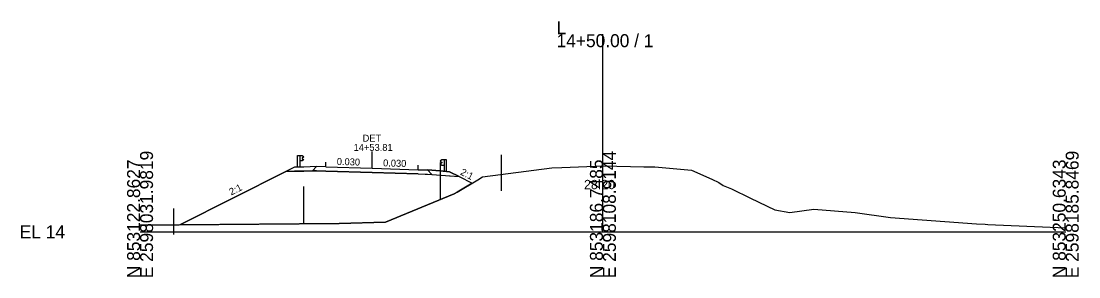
# Model space of a CAD drawing. Extents: x -26 to 1203, y -10 to 9526.
# Drawn here: x -25.7 to 202.8, y 4490.3 to 4545.4 of the extents above; entities that cross this region are included whole.
import ezdxf

# ---------------------------------------------------------------- set-up
doc = ezdxf.new("R2010")
doc.units = 0
for name, color, linetype in [('Exist Cross Section Cell', 7, 'Continuous'), ('Exist XS Center Line Elevation Label', 7, 'Continuous'), ('Exist XS Ground Line', 7, 'Continuous'), ('Prop XS Alignment Label', 7, 'Continuous'), ('Prop XS Earthwork Shape', 7, 'Continuous'), ('Prop XS EOT Tick Mark', 7, 'Continuous'), ('Prop XS Exc Vertical Line 1', 7, 'Continuous'), ('Prop XS Exc Vertical Line 2', 7, 'Continuous'), ('Prop XS Finish Grade', 7, 'Continuous'), ('Prop XS Finish Grade Earthwork', 7, 'Continuous'), ('Prop XS Finish Grade Paved Shoulder', 7, 'Continuous'), ('Prop XS Finish Grade Pavement', 7, 'Continuous'), ('Prop XS Guardrail', 7, 'Continuous'), ('Prop XS Pvmt Edge Slope', 7, 'Continuous'), ('Prop XS SE Text', 7, 'Continuous'), ('Prop XS Side Slope Text', 7, 'Continuous'), ('Prop XS Station Labels', 7, 'Continuous'), ('Prop XS Subgrade Earthwork', 7, 'Continuous'), ('Scratch_Level_1', 7, 'Continuous'), ('Scratch_Level_2', 7, 'Continuous')]:
    doc.layers.add(name, color=color, linetype=linetype)

msp = doc.modelspace()

# ---------------------------------------------------------------- linework, layer by layer
at = {"layer": 'Exist Cross Section Cell'}
for p, q in [((100, 4500), (100, 4542.62)), ((0, 4500), (100, 4500)), ((100, 4500), (200, 4500))]:
    msp.add_line(p, q, dxfattribs=at)
at = {"layer": 'Exist XS Ground Line'}
for p, q in [((73.97, 4511.84), (88.94, 4513.8)), ((88.94, 4513.8), (91.12, 4513.88)), ((91.12, 4513.88), (100.1, 4514.21)), ((100.1, 4514.21), (108.82, 4514.04)), ((108.82, 4514.04), (111.24, 4513.99)), ((111.24, 4513.99), (112.83, 4513.88)), ((112.83, 4513.88), (119.15, 4513.32)), ((72.95, 4511.22), (73.97, 4511.84)), ((119.15, 4513.32), (123.51, 4511.36)), ((123.51, 4511.36), (125.03, 4510.64)), ((68.54, 4508.52), (72.95, 4511.22)), ((125.03, 4510.64), (126.01, 4509.98)), ((126.01, 4509.98), (127.79, 4509.31)), ((127.79, 4509.31), (131.93, 4507.23)), ((53.01, 4502.09), (67.86, 4508.19)), ((67.86, 4508.19), (68.54, 4508.52)), ((131.93, 4507.23), (137.18, 4504.72)), ((137.18, 4504.72), (140.41, 4504.19)), ((140.41, 4504.19), (145.55, 4504.89)), ((145.55, 4504.89), (154.54, 4504.14)), ((43.04, 4501.81), (53.01, 4502.09)), ((154.54, 4504.14), (162.17, 4503.09)), ((162.17, 4503.09), (180.73, 4501.76)), ((0, 4501.48), (8.39, 4501.53)), ((8.39, 4501.53), (43.04, 4501.81)), ((180.73, 4501.76), (182.59, 4501.65)), ((182.59, 4501.65), (183.14, 4501.61)), ((183.14, 4501.61), (200, 4500.84))]:
    msp.add_line(p, q, dxfattribs=at)
at = {"layer": 'Prop XS Earthwork Shape'}
msp.add_lwpolyline([(66.86, 4512.09), (68.93, 4511.92), (71.78, 4510.5), (68.54, 4508.52), (67.86, 4508.19), (53.01, 4502.09), (43.04, 4501.81), (8.59, 4501.54), (31.51, 4513), (33.35, 4513.05), (35.35, 4513.11), (37.23, 4513.17), (38.12, 4513.14), (40.12, 4513.08), (50.12, 4512.78), (60.12, 4512.48), (62.12, 4512.42), (65.06, 4512.23)], close=True, dxfattribs=at)
at = {"layer": 'Prop XS EOT Tick Mark'}
for p, q in [((40.12, 4514), (40.12, 4515)), ((60.12, 4513.4), (60.12, 4514.4))]:
    msp.add_line(p, q, dxfattribs=at)
at = {"layer": 'Prop XS Exc Vertical Line 1'}
msp.add_line((7.22, 4505.04), (7.22, 4499.46), dxfattribs=at)
at = {"layer": 'Prop XS Exc Vertical Line 2'}
msp.add_line((78, 4516.6), (78, 4508.87), dxfattribs=at)
at = {"layer": 'Prop XS Finish Grade'}
for p, q in [((33.35, 4513.92), (31.51, 4513)), ((35.35, 4513.98), (33.35, 4513.92)), ((38.12, 4514.06), (35.35, 4513.98)), ((62.12, 4513.34), (64.86, 4513.12)), ((64.86, 4513.12), (66.86, 4512.96)), ((66.86, 4512.96), (68.93, 4511.92))]:
    msp.add_line(p, q, dxfattribs=at)
at = {"layer": 'Prop XS Finish Grade Earthwork'}
for p, q in [((31.51, 4513), (8.59, 4501.54)), ((68.93, 4511.92), (71.78, 4510.5))]:
    msp.add_line(p, q, dxfattribs=at)
at = {"layer": 'Prop XS Finish Grade Paved Shoulder'}
for p, q in [((40.12, 4514), (38.12, 4514.06)), ((60.12, 4513.4), (62.12, 4513.34))]:
    msp.add_line(p, q, dxfattribs=at)
at = {"layer": 'Prop XS Finish Grade Pavement'}
for p, q in [((40.12, 4514), (50.12, 4513.7)), ((50.12, 4513.7), (60.12, 4513.4))]:
    msp.add_line(p, q, dxfattribs=at)
at = {"layer": 'Prop XS Guardrail'}
for p, q in [((34.03, 4516.44), (34.53, 4516.44)), ((34.03, 4513.94), (34.03, 4516.44)), ((34.53, 4516.44), (35.03, 4516.44)), ((34.53, 4516.44), (34.53, 4513.94)), ((35.03, 4516.44), (35.32, 4516.24)), ((35.32, 4516.12), (35.03, 4515.92)), ((35.03, 4515.92), (35.03, 4515.82)), ((35.03, 4515.82), (35.32, 4515.62)), ((35.32, 4516.24), (35.35, 4516.18)), ((35.35, 4516.18), (35.32, 4516.12)), ((35.03, 4515.3), (34.53, 4515.3)), ((35.32, 4515.5), (35.03, 4515.3)), ((35.32, 4515.62), (35.35, 4515.56)), ((35.35, 4515.56), (35.32, 4515.5)), ((64.89, 4515.31), (64.86, 4515.25)), ((64.86, 4515.25), (64.89, 4515.19)), ((64.89, 4514.7), (64.86, 4514.64)), ((64.86, 4514.64), (64.89, 4514.58)), ((65.18, 4515.51), (64.89, 4515.31)), ((64.89, 4515.19), (65.18, 4514.99)), ((65.18, 4514.9), (64.89, 4514.7)), ((64.89, 4514.58), (65.18, 4514.38)), ((65.68, 4515.51), (65.18, 4515.51)), ((65.18, 4514.99), (65.18, 4514.9)), ((65.18, 4514.38), (65.68, 4514.38)), ((66.18, 4515.51), (65.68, 4515.51)), ((65.68, 4515.51), (65.68, 4513.01)), ((66.18, 4513.01), (66.18, 4515.51))]:
    msp.add_line(p, q, dxfattribs=at)
at = {"layer": 'Prop XS Pvmt Edge Slope'}
for p, q in [((38.12, 4514.06), (37.23, 4513.17)), ((62.12, 4513.34), (63.06, 4512.39))]:
    msp.add_line(p, q, dxfattribs=at)
at = {"layer": 'Prop XS Side Slope Text'}
msp.add_line((50.12, 4513.7), (50.12, 4517.35), dxfattribs=at)
at = {"layer": 'Prop XS Subgrade Earthwork'}
for p, q in [((33.35, 4513.05), (31.51, 4513)), ((35.35, 4513.11), (33.35, 4513.05)), ((37.23, 4513.17), (35.35, 4513.11)), ((38.12, 4513.14), (37.23, 4513.17)), ((40.12, 4513.08), (38.12, 4513.14)), ((50.12, 4512.78), (40.12, 4513.08)), ((60.12, 4512.48), (50.12, 4512.78)), ((60.12, 4512.48), (63.06, 4512.39)), ((63.06, 4512.39), (68.93, 4511.92))]:
    msp.add_line(p, q, dxfattribs=at)
at = {"layer": 'Scratch_Level_1'}
for points in [[(33.35, 4513.92), (31.51, 4513), (33.35, 4513.05), (35.35, 4513.11), (37.23, 4513.17), (38.12, 4514.06), (35.35, 4513.98)], [(62.12, 4513.34), (63.06, 4512.39), (68.93, 4511.92), (66.86, 4512.96), (64.86, 4513.12)]]:
    msp.add_lwpolyline(points, close=True, dxfattribs=at)
at = {"layer": 'Scratch_Level_2'}
for p, q in [((64.86, 4514.95), (64.86, 4506.95)), ((35.34, 4509.75), (35.34, 4501.75))]:
    msp.add_line(p, q, dxfattribs=at)

# ---------------------------------------------------------------- texts
at = {"layer": 'Exist Cross Section Cell'}
for s, p in [('L', (90, 4542.62)), ('14+50.00 / 1', (90, 4539.82)), ('EL 14', (-26, 4498.6))]:
    msp.add_text(s, height=2.8, dxfattribs=at).set_placement(p)
for s, p in [('E 2598031.9819', (2.8, 4490)), ('E 2598108.9144', (102.8, 4490)), ('E 2598185.8469', (202.8, 4490)), ('N 853122.8627', (0, 4490)), ('N 853186.7485', (100, 4490)), ('N 853250.6343', (200, 4490))]:
    msp.add_text(s, height=2.8, rotation=90, dxfattribs=at).set_placement(p)
at = {"layer": 'Exist XS Center Line Elevation Label'}
msp.add_text('28.20', height=2, dxfattribs=at).set_placement((95.93, 4509.2))
at = {"layer": 'Prop XS Alignment Label'}
msp.add_text('DET', height=1.5, dxfattribs=at).set_placement((48.09, 4519.45))
at = {"layer": 'Prop XS SE Text'}
for rotation, p in [(358.2788, (42.49, 4514.43)), (358.2787, (52.49, 4514.13))]:
    msp.add_text('0.030', height=1.5, rotation=rotation, dxfattribs=at).set_placement(p)
at = {"layer": 'Prop XS Side Slope Text'}
for rotation, p in [(333.4349, (69.07, 4512.41)), (26.5651, (19.71, 4507.84))]:
    msp.add_text('2:1', height=1.5, rotation=rotation, dxfattribs=at).set_placement(p)
at = {"layer": 'Prop XS Station Labels'}
msp.add_text('14+53.81', height=1.5, dxfattribs=at).set_placement((46.15, 4517.45))

doc.saveas('drawing.dxf')
